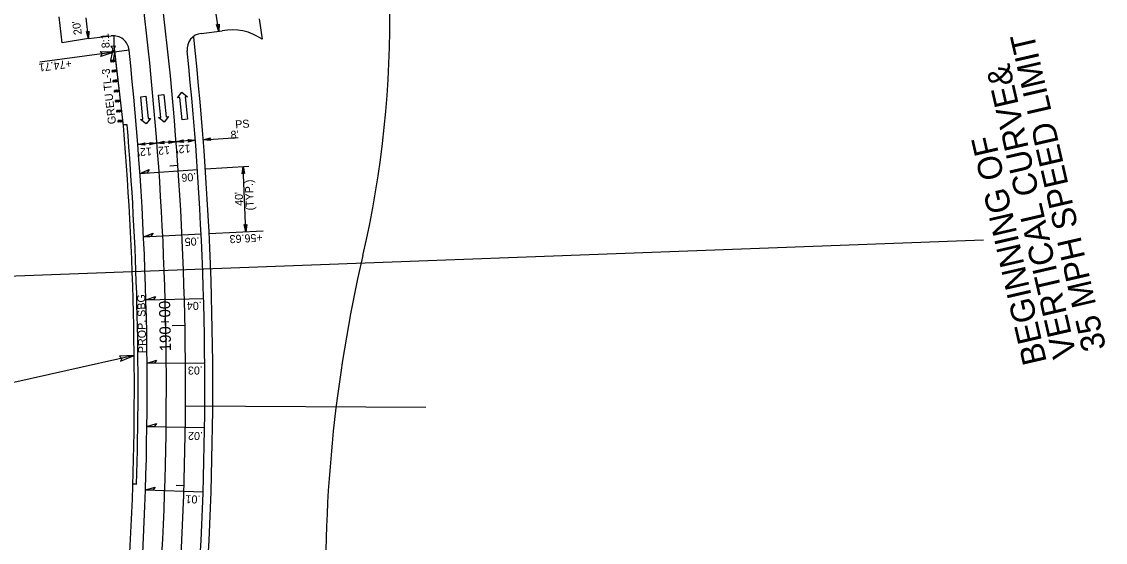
# Model space of a CAD drawing. Extents: x 472216 to 481979, y 489069 to 507339.
# Drawn here: x 474424 to 475100, y 504358 to 504683 of the extents above; entities that cross this region are included whole.
import ezdxf

# ---------------------------------------------------------------- set-up
doc = ezdxf.new("R2010")
doc.units = 0
for name, color, linetype in [('Prop Drainage Structure Drop Inlet Grate 2 Narrow Slots and Sag Grates 840 24 CELL', 7, 'Continuous'), ('Prop Drainage Structure Drop Inlet Grate 2 Wide Slots and Sag Grates 840 22 Label', 7, 'Continuous'), ('Prop Drainage Structure Outlet Berm Ditch 850 10 CELL', 7, 'Continuous'), ('Prop Drainage Structure Pipe CSP 15in', 7, 'Continuous'), ('Prop Drainage Structure Pipe Plug CELL', 7, 'Continuous'), ('Prop Drainage Structure Pipe RCP 24in Class III Label', 7, 'Continuous'), ('Prop Drainage Structure Pipe Side Drain 15in Label', 7, 'Continuous'), ('Prop Drainage Structure Tops and Inverts LABEL', 7, 'Continuous'), ('Prop Earthen Structure False Sump CELL', 7, 'Continuous'), ('Prop Erosion Embankment Toe Protection CELL', 7, 'Continuous'), ('Prop Erosion Embankment Toe Protection Label', 7, 'Continuous'), ('Sheet Block Revision CELL', 7, 'Continuous'), ('Sheet Block Title CELL', 7, 'Continuous'), ('Sheet North Arrow Point CELL', 7, 'Continuous'), ('Sheet PE Seal Cell', 7, 'Continuous'), ('Sheet Profile Grid Major CELL', 7, 'Continuous'), ('Sheet Profile Grid Minor CELL', 7, 'Continuous')]:
    doc.layers.add(name, color=color, linetype=linetype)

msp = doc.modelspace()

# ---------------------------------------------------------------- linework, layer by layer
at = {"layer": 'Prop Drainage Structure Drop Inlet Grate 2 Narrow Slots and Sag Grates 840 24 CELL'}
for p, q in [((474538.34, 504590.75), (474565.55, 504592.6)), ((474563.62, 504551.57), (474561.86, 504592.35)), ((474540.68, 504550.48), (474574.49, 504552.09))]:
    msp.add_line(p, q, dxfattribs=at)
for points in [[(474497.44, 504587.96), (474503.29, 504590.37), (474502.05, 504588.28)], [(474561.28, 504587.82), (474561.86, 504592.35), (474562.86, 504587.87), (474562.04, 504588.41)], [(474564.18, 504556.11), (474563.62, 504551.57), (474562.61, 504556.06), (474563.43, 504555.52)], [(474499.72, 504548.51), (474505.62, 504550.8), (474504.34, 504548.74)], [(474501.22, 504509.03), (474507.16, 504511.19), (474505.84, 504509.15)], [(474501.91, 504469.52), (474507.9, 504471.56), (474506.54, 504469.55)], [(474501.81, 504430), (474507.84, 504431.93), (474506.44, 504429.95)], [(474500.92, 504390.5), (474506.98, 504392.3), (474505.54, 504390.34)]]:
    msp.add_lwpolyline(points, close=True, dxfattribs=at)
at = {"layer": 'Prop Drainage Structure Drop Inlet Grate 2 Wide Slots and Sag Grates 840 22 Label'}
for p, q in [((474497.44, 504587.96), (474533.35, 504590.41)), ((474499.72, 504548.51), (474535.68, 504550.24)), ((474501.22, 504509.03), (474537.2, 504510.02)), ((474501.91, 504469.52), (474537.91, 504469.79)), ((474501.81, 504430), (474537.81, 504429.55)), ((474500.92, 504390.5), (474536.9, 504389.32))]:
    msp.add_line(p, q, dxfattribs=at)
at = {"layer": 'Prop Drainage Structure Outlet Berm Ditch 850 10 CELL'}
for points in [[(474546.88, 504681.18), (474546.83, 504676.62), (474545.32, 504680.96), (474546.2, 504680.52)], [(474465.57, 504676.69), (474465.33, 504672.13), (474464, 504676.53), (474464.86, 504676.05)], [(474472.61, 504664.16), (474481.74, 504663.83), (474472.99, 504661.03), (474473.91, 504662.77)], [(474541.56, 504608.54), (474537.01, 504609.01), (474541.47, 504610.12), (474540.95, 504609.28)], [(474500.67, 504605.58), (474496.12, 504606.03), (474500.58, 504607.15), (474500.06, 504606.31)], [(474503.55, 504607.35), (474508.09, 504606.91), (474503.64, 504605.78), (474504.15, 504606.62)], [(474512.63, 504606.46), (474508.09, 504606.91), (474512.54, 504608.03), (474512.03, 504607.19)], [(474515.51, 504608.23), (474520.06, 504607.79), (474515.6, 504606.66), (474516.12, 504607.5)], [(474524.6, 504607.34), (474520.06, 504607.79), (474524.51, 504608.91), (474524, 504608.07)], [(474527.48, 504609.11), (474532.03, 504608.67), (474527.57, 504607.54), (474528.09, 504608.38)], [(474485.42, 504470.85), (474493.87, 504474.32), (474484.69, 504473.91), (474486.16, 504472.6)]]:
    msp.add_lwpolyline(points, close=True, dxfattribs=at)
at = {"layer": 'Prop Drainage Structure Pipe Plug CELL'}
for p, q in [((474482.23, 504667.49), (474479.3, 504667.2)), ((474479.3, 504667.2), (474480.27, 504666.11)), ((474481.7, 504664.67), (474480.21, 504664.5)), ((474480.33, 504663.5), (474480.21, 504664.5)), ((474480.21, 504664.5), (474481.82, 504663.67)), ((474480.27, 504666.11), (474480.47, 504664.07)), ((474480.33, 504663.5), (474480.27, 504664)), ((474481.7, 504664.67), (474480.33, 504663.5)), ((474481.82, 504663.67), (474480.33, 504663.5)), ((474480.47, 504664.07), (474481.08, 504664.13)), ((474480.86, 504658.63), (474481.82, 504663.67)), ((474481.08, 504664.13), (474481.68, 504664.2)), ((474481.48, 504666.23), (474482.23, 504667.49)), ((474481.68, 504664.2), (474481.48, 504666.23)), ((474487.15, 504617.73), (474481.76, 504664.17)), ((474479.34, 504658.45), (474480.33, 504663.5)), ((474482.38, 504658.81), (474479.34, 504658.45)), ((474479.46, 504657.46), (474479.34, 504658.45)), ((474479.34, 504658.45), (474480.98, 504657.64)), ((474480.86, 504658.63), (474479.46, 504657.46)), ((474482.5, 504657.81), (474479.46, 504657.46)), ((474480.98, 504657.64), (474480.86, 504658.63)), ((474482.5, 504657.81), (474480.86, 504658.63)), ((474480.98, 504657.64), (474482.38, 504658.81)), ((474483.11, 504652.55), (474480.13, 504652.2)), ((474480.25, 504651.21), (474480.13, 504652.2)), ((474480.13, 504652.2), (474481.74, 504651.38)), ((474481.62, 504652.37), (474480.25, 504651.21)), ((474483.23, 504651.55), (474480.25, 504651.21)), ((474481.74, 504651.38), (474481.62, 504652.37)), ((474483.23, 504651.55), (474481.62, 504652.37)), ((474481.74, 504651.38), (474483.11, 504652.55)), ((474483.84, 504646.29), (474480.72, 504645.93)), ((474480.84, 504644.93), (474480.72, 504645.93)), ((474480.72, 504645.93), (474482.4, 504645.11)), ((474482.28, 504646.11), (474480.84, 504644.93)), ((474483.95, 504645.29), (474480.84, 504644.93)), ((474482.4, 504645.11), (474482.28, 504646.11)), ((474483.95, 504645.29), (474482.28, 504646.11)), ((474482.4, 504645.11), (474483.84, 504646.29)), ((474484.56, 504640.03), (474481.55, 504639.68)), ((474481.66, 504638.69), (474481.55, 504639.68)), ((474481.55, 504639.68), (474483.17, 504638.86)), ((474483.06, 504639.85), (474481.66, 504638.69)), ((474484.68, 504639.04), (474481.66, 504638.69)), ((474483.17, 504638.86), (474483.06, 504639.85)), ((474484.68, 504639.04), (474483.06, 504639.85)), ((474483.17, 504638.86), (474484.56, 504640.03)), ((474484.68, 504639.04), (474484.56, 504640.03)), ((474485.29, 504633.77), (474482.26, 504633.42)), ((474482.38, 504632.42), (474482.26, 504633.42)), ((474482.26, 504633.42), (474483.89, 504632.6)), ((474483.78, 504633.59), (474482.38, 504632.42)), ((474485.41, 504632.78), (474482.38, 504632.42)), ((474483.89, 504632.6), (474483.78, 504633.59)), ((474485.41, 504632.78), (474483.78, 504633.59)), ((474483.89, 504632.6), (474485.29, 504633.77)), ((474486.02, 504627.51), (474482.99, 504627.16)), ((474483.1, 504626.16), (474482.99, 504627.16)), ((474482.99, 504627.16), (474484.62, 504626.34)), ((474484.5, 504627.33), (474483.1, 504626.16)), ((474486.13, 504626.52), (474483.1, 504626.16)), ((474484.62, 504626.34), (474484.5, 504627.33)), ((474486.13, 504626.52), (474484.5, 504627.33)), ((474484.62, 504626.34), (474486.02, 504627.51)), ((474486.74, 504621.25), (474483.77, 504620.91)), ((474483.88, 504619.91), (474483.77, 504620.91)), ((474483.77, 504620.91), (474485.37, 504620.08)), ((474485.25, 504621.08), (474483.88, 504619.91)), ((474486.86, 504620.26), (474483.88, 504619.91)), ((474486.74, 504621.25), (474485.25, 504621.08)), ((474485.37, 504620.08), (474485.25, 504621.08)), ((474485.25, 504621.08), (474486.86, 504620.26)), ((474485.37, 504620.08), (474486.74, 504621.25)), ((474486.86, 504620.26), (474486.74, 504621.25))]:
    msp.add_line(p, q, dxfattribs=at)
at = {"layer": 'Prop Drainage Structure Pipe RCP 24in Class III Label'}
for p, q in [((474448.91, 504669.55), (474447.01, 504685.78)), ((474571.83, 504684.54), (474573.7, 504671.7)), ((474465.33, 504672.13), (474448.91, 504669.55)), ((474465.33, 504672.13), (474479.55, 504673.81)), ((474535.73, 504675.37), (474548.81, 504676.89)), ((474489.44, 504618.39), (474487.11, 504618.2)), ((474495.36, 504394), (474493.03, 504394.07))]:
    msp.add_line(p, q, dxfattribs=at)
for centre, radius, start, end in [((474555.47, 504646.51), 31.1, 54.10172, 102.35332), ((474480.72, 504663.88), 10, 6.15452, 96.74742), ((474536.88, 504665.44), 10, 96.59791, 186.02694), ((472540.97, 504454.71), 1961, 356.96875, 6.15452), ((472540.97, 504454.71), 1997, 356.96875, 6.02694)]:
    msp.add_arc(centre, radius, start, end, dxfattribs=at)
at = {"layer": 'Prop Drainage Structure Pipe Side Drain 15in Label'}
for p, q in [((474509.1, 504636.9), (474512.38, 504637.24)), ((474510.52, 504622.97), (474509.1, 504636.9)), ((474512.38, 504637.24), (474513.8, 504623.31)), ((474520.88, 504635.23), (474523.64, 504638.68)), ((474523.64, 504638.68), (474527.14, 504635.87)), ((474497.92, 504635.76), (474501.2, 504636.1)), ((474499.34, 504621.84), (474497.92, 504635.76)), ((474501.2, 504636.1), (474502.62, 504622.17)), ((474522.37, 504635.39), (474520.88, 504635.23)), ((474523.79, 504621.46), (474522.37, 504635.39)), ((474527.14, 504635.87), (474525.65, 504635.72)), ((474525.65, 504635.72), (474527.07, 504621.79)), ((474515.29, 504623.46), (474512.53, 504620.01)), ((474513.8, 504623.31), (474515.29, 504623.46)), ((474497.85, 504621.68), (474499.34, 504621.84)), ((474501.35, 504618.87), (474497.85, 504621.68)), ((474504.11, 504622.32), (474501.35, 504618.87)), ((474502.62, 504622.17), (474504.11, 504622.32)), ((474509.03, 504622.82), (474510.52, 504622.97)), ((474512.53, 504620.01), (474509.03, 504622.82)), ((474527.07, 504621.79), (474523.79, 504621.46))]:
    msp.add_line(p, q, dxfattribs=at)
at = {"layer": 'Prop Drainage Structure Tops and Inverts LABEL'}
msp.add_arc((472540.97, 504454.71), 1953, 356.96875, 4.78809, dxfattribs=at)
at = {"layer": 'Prop Earthen Structure False Sump CELL'}
msp.add_arc((472540.97, 504454.71), 1955.33, 358.22065, 4.80172, dxfattribs=at)
at = {"layer": 'Prop Erosion Embankment Toe Protection CELL'}
msp.add_line((474487.15, 504617.73), (474481.35, 504667.4), dxfattribs=at)
for radius, end in [(2002, 6.25868), (1953, 4.78809)]:
    msp.add_arc((472540.97, 504454.71), radius, 356.96875, end, dxfattribs=at)
msp.add_spline([(474481.35, 504667.4), (474481.35, 504667.83), (474481.36, 504668.26), (474481.37, 504668.69), (474481.38, 504669.12), (474481.38, 504669.55), (474481.39, 504669.97), (474481.4, 504670.4), (474481.4, 504670.83), (474481.41, 504671.26), (474481.42, 504671.69), (474481.42, 504672.12), (474481.43, 504672.55), (474481.43, 504672.98), (474481.44, 504673.4), (474481.45, 504673.83), (474481.45, 504673.85)], degree=3, dxfattribs=at)
at = {"layer": 'Prop Erosion Embankment Toe Protection Label'}
msp.add_arc((472540.97, 504454.71), 1973, 356.96875, 14.25965, dxfattribs=at)
at = {"layer": 'Sheet Block Revision CELL'}
for p, q in [((474546.83, 504676.62), (474543.56, 504696.88)), ((474465.33, 504672.13), (474463.81, 504684.98)), ((474490.67, 504664.95), (474434.95, 504657.4)), ((474537.01, 504609.01), (474558.78, 504610.5)), ((474532.03, 504608.67), (474496.12, 504606.03)), ((474493.87, 504474.32), (474356.43, 504443.63))]:
    msp.add_line(p, q, dxfattribs=at)
at = {"layer": 'Sheet Block Title CELL'}
for p, q in [((474024.95, 504509.58), (475024.27, 504546.52)), ((474525.93, 504443.07), (474675.93, 504442.19))]:
    msp.add_line(p, q, dxfattribs=at)
at = {"layer": 'Sheet North Arrow Point CELL'}
for centre, radius, start, end in [((474003.55, 504683.86), 650, 346.91582, 43.31339), ((472540.97, 504454.71), 1985, 356.96875, 14.25965), ((475513.31, 504332.97), 900, 166.91582, 182.02426)]:
    msp.add_arc(centre, radius, start, end, dxfattribs=at)
at = {"layer": 'Sheet PE Seal Cell'}
for p, q in [((474521.15, 504592.96), (474516.16, 504592.61)), ((474525.01, 504393.08), (474520.01, 504393.23))]:
    msp.add_line(p, q, dxfattribs=at)
at = {"layer": 'Sheet Profile Grid Minor CELL'}
msp.add_line((474525.6, 504493.07), (474517.6, 504492.91), dxfattribs=at)

# ---------------------------------------------------------------- texts
at = {"layer": 'Prop Drainage Structure Drop Inlet Grate 2 Narrow Slots and Sag Grates 840 24 CELL'}
for s, rotation, p in [('.06', 183.89625, (474532.47, 504588.32)), ('(TYP.)', 92.49989, (474568.71, 504564.97)), ("40'", 92.49989, (474562.02, 504567.85)), ('+56.63', 182.74168, (474573.98, 504550.41)), ('.05', 182.74168, (474534.58, 504548.15)), ('.04', 181.5871, (474535.99, 504507.96)), ('.03', 180.43253, (474536.72, 504467.53)), ('.02', 179.2734, (474536.85, 504426.62)), ('.01', 178.12338, (474535.31, 504386.96))]:
    msp.add_text(s, height=5, rotation=rotation, dxfattribs=at).set_placement(p)
at = {"layer": 'Prop Drainage Structure Pipe CSP 15in'}
for s, rotation, p in [("20'", 99.16906, (474461.26, 504674.86)), ('8:1', 94.8766, (474478.64, 504666.35)), ('+74.71', 187.51203, (474454.48, 504659.05)), ('PS', 3.92502, (474557.13, 504616.05)), ("8'", 3.92502, (474554.26, 504609.5)), ("12'", 184.20526, (474504.72, 504604.23)), ("12'", 184.20526, (474516.04, 504605.07)), ("12'", 184.20526, (474528.79, 504606)), ('PROP. SBG', 91.10468, (474501.4, 504475.9))]:
    msp.add_text(s, height=5, rotation=rotation, dxfattribs=at).set_placement(p)
at = {"layer": 'Prop Drainage Structure Pipe Plug CELL'}
msp.add_text('GREU TL-3', height=5, rotation=96.69969, dxfattribs=at).set_placement((474482.57, 504619.01))
at = {"layer": 'Sheet Block Title CELL'}
for s, p in [('35 MPH SPEED LIMIT', (475101.01, 504478.97)), ('VERTICAL CURVE& ', (475082.48, 504474.7)), ('BEGINNING OF ', (475063.95, 504470.43))]:
    msp.add_text(s, height=15, rotation=102.98112, dxfattribs=at).set_placement(p)
at = {"layer": 'Sheet Profile Grid Major CELL'}
msp.add_text('190+00', height=7, rotation=91.10709, dxfattribs=at).set_placement((474516.91, 504477.08))

doc.saveas('drawing.dxf')
